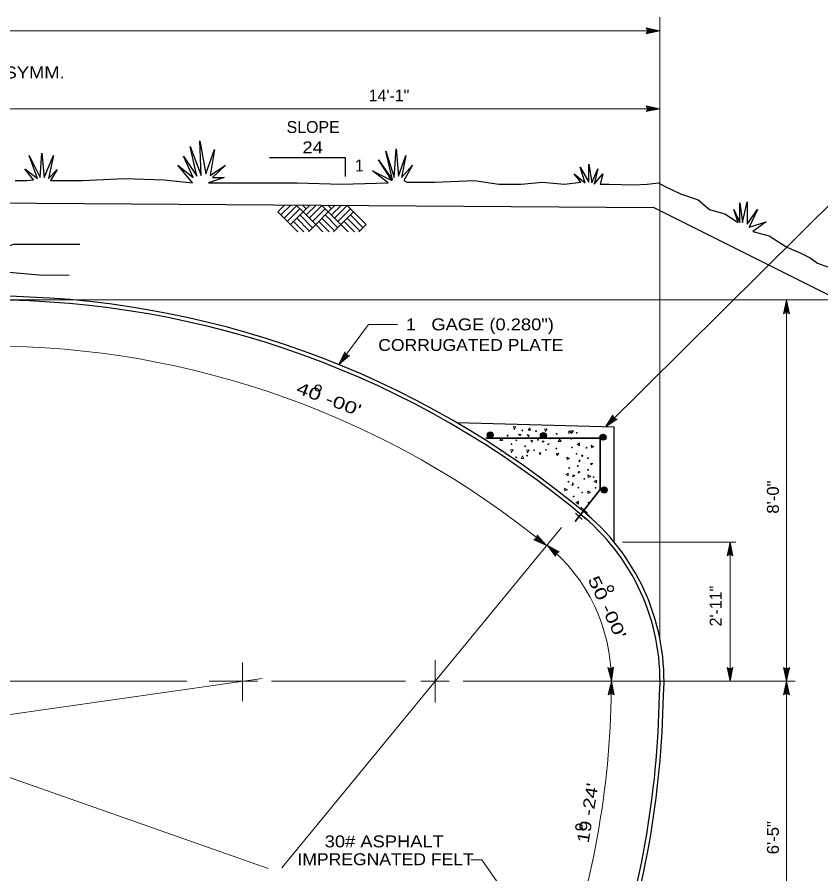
# Model space of a CAD drawing. Extents: x -24.3 to 17.7, y -17.6 to 12.4.
# Drawn here: x -9.61 to -1.17, y -10.08 to -1.09 of the extents above; entities that cross this region are included whole.
import ezdxf
from ezdxf.enums import TextEntityAlignment as Align

# ---------------------------------------------------------------- set-up
doc = ezdxf.new("R2010")
doc.units = 0
doc.header["$LTSCALE"] = 0.05
doc.layers.add('1', color=7, linetype='Continuous', lineweight=13)
doc.layers.add('2', color=7, linetype='Continuous', lineweight=13)

msp = doc.modelspace()

# ---------------------------------------------------------------- linework, layer by layer
at = {"layer": '1'}
for p, q in [((-2.86269, -7.6306), (-2.86269, -1.0886)), ((-16.95069, -1.2326), (-2.86269, -1.2326)), ((-2.86269, -1.2326), (-3.00669, -1.2016)), ((-2.86269, -1.2326), (-3.00669, -1.2636)), ((-2.89969, -1.2326), (-2.99369, -1.2126)), ((-2.98469, -1.2326), (-2.99369, -1.2126)), ((-2.89969, -1.2326), (-2.99369, -1.2526)), ((-2.99369, -1.2526), (-2.98469, -1.2326)), ((-2.93569, -1.2326), (-2.98069, -1.2236)), ((-2.97669, -1.2326), (-2.98069, -1.2236)), ((-2.93569, -1.2326), (-2.98069, -1.2426)), ((-2.98069, -1.2426), (-2.97669, -1.2326)), ((-2.86269, -2.0496), (-3.00669, -2.0186)), ((-2.86269, -2.0496), (-3.00669, -2.0806)), ((-2.89969, -2.0496), (-2.99369, -2.0296)), ((-2.98469, -2.0496), (-2.99369, -2.0296)), ((-2.89969, -2.0496), (-2.99369, -2.0696)), ((-2.99369, -2.0696), (-2.98469, -2.0496)), ((-2.93569, -2.0496), (-2.98069, -2.0406)), ((-2.97669, -2.0496), (-2.98069, -2.0406)), ((-2.93569, -2.0496), (-2.98069, -2.0596)), ((-2.98069, -2.0596), (-2.97669, -2.0496)), ((-3.43569, -5.3886), (-0.97569, -2.9496)), ((-6.87269, -3.1326), (-6.80169, -3.0616)), ((-6.83969, -3.1656), (-6.73569, -3.0616)), ((-6.80669, -3.1986), (-6.67369, -3.0666)), ((-6.77369, -3.2326), (-6.64069, -3.0996)), ((-6.74069, -3.2656), (-6.60769, -3.1326)), ((-6.60769, -3.1326), (-6.67869, -3.0616)), ((-6.57469, -3.0996), (-6.61269, -3.0616)), ((-6.60769, -3.1326), (-6.53669, -3.0616)), ((-6.60769, -3.1326), (-6.53669, -3.0616)), ((-6.47469, -3.2656), (-6.60769, -3.1326)), ((-6.57469, -3.1656), (-6.47069, -3.0616)), ((-6.54169, -3.0666), (-6.54669, -3.0616)), ((-6.54169, -3.1986), (-6.40869, -3.0666)), ((-6.50869, -3.2326), (-6.37569, -3.0996)), ((-6.47469, -3.2656), (-6.34269, -3.1326)), ((-6.34269, -3.1326), (-6.41369, -3.0616)), ((-6.30969, -3.0996), (-6.34769, -3.0616)), ((-6.34269, -3.1326), (-6.27169, -3.0616)), ((-6.30969, -3.1656), (-6.20469, -3.0616)), ((-6.27669, -3.0666), (-6.28069, -3.0616)), ((-6.27669, -3.1986), (-6.14369, -3.0666)), ((-6.24269, -3.2326), (-6.11069, -3.0996)), ((-6.20969, -3.2656), (-6.07769, -3.1326)), ((-6.07769, -3.1326), (-6.14869, -3.0616)), ((-5.94469, -3.2656), (-6.07769, -3.1326)), ((-6.59769, -3.3416), (-6.70769, -3.2326)), ((-6.54169, -3.3316), (-6.67369, -3.1986)), ((-6.50869, -3.2986), (-6.64069, -3.1656)), ((-6.33269, -3.3416), (-6.44169, -3.2326)), ((-6.27669, -3.3316), (-6.40869, -3.1986)), ((-6.24269, -3.2986), (-6.37569, -3.1656)), ((-6.06669, -3.3416), (-6.17669, -3.2326)), ((-6.01069, -3.3316), (-6.14369, -3.1986)), ((-5.97769, -3.2986), (-6.11069, -3.1656)), ((-6.55169, -3.3416), (-6.47469, -3.2656)), ((-6.39869, -3.3416), (-6.47469, -3.2656)), ((-6.28669, -3.3416), (-6.20969, -3.2656)), ((-6.02169, -3.3416), (-5.94469, -3.2656)), ((-9.90969, -4.0576), (-0.82769, -4.0576)), ((-1.53569, -4.0576), (-1.56669, -4.2016)), ((-1.53569, -4.0946), (-1.55569, -4.1886)), ((-1.53569, -4.1306), (-1.54469, -4.1756)), ((-1.53569, -4.0576), (-1.50469, -4.2016)), ((-1.53569, -4.0946), (-1.51569, -4.1886)), ((-1.53569, -4.1306), (-1.52569, -4.1756)), ((-1.53569, -4.1796), (-1.55569, -4.1886)), ((-1.53569, -4.1716), (-1.54469, -4.1756)), ((-1.52569, -4.1756), (-1.53569, -4.1716)), ((-1.51569, -4.1886), (-1.53569, -4.1796)), ((-5.92169, -4.3166), (-5.61569, -4.3166)), ((-6.23169, -4.7366), (-6.12169, -4.6396)), ((-6.20969, -4.7066), (-6.16969, -4.6196)), ((-6.20969, -4.7066), (-6.13769, -4.6426)), ((-6.18869, -4.6776), (-6.16969, -4.6356)), ((-6.18869, -4.6776), (-6.15469, -4.6466)), ((-6.16969, -4.6196), (-6.15969, -4.6386)), ((-6.16969, -4.6356), (-6.16369, -4.6446)), ((-6.16369, -4.6446), (-6.15469, -4.6466)), ((-6.15969, -4.6386), (-6.13769, -4.6426)), ((-3.43569, -5.3886), (-3.35569, -5.2656)), ((-3.40969, -5.3626), (-3.35669, -5.2826)), ((-3.38369, -5.3376), (-3.35869, -5.2986)), ((-3.35869, -5.2986), (-3.35469, -5.3086)), ((-3.35669, -5.2826), (-3.34869, -5.3026)), ((-3.34869, -5.3026), (-3.32869, -5.3106)), ((-3.43569, -5.3886), (-3.31169, -5.3096)), ((-3.40969, -5.3626), (-3.32869, -5.3106)), ((-3.38369, -5.3376), (-3.34569, -5.3116)), ((-3.35469, -5.3086), (-3.34569, -5.3116)), ((-6.82969, -10.0186), (-3.89669, -6.4466)), ((-4.16969, -6.5746), (-4.15069, -6.5646)), ((-4.15069, -6.5646), (-4.14669, -6.5426)), ((-4.05269, -6.6366), (-4.14969, -6.5266)), ((-4.08269, -6.6146), (-4.14669, -6.5426)), ((-4.14469, -6.5686), (-4.14269, -6.5596)), ((-4.11169, -6.5936), (-4.14269, -6.5596)), ((-4.05269, -6.6366), (-4.18669, -6.5756)), ((-4.08269, -6.6146), (-4.16969, -6.5746)), ((-4.15369, -6.5746), (-4.14469, -6.5686)), ((-4.11169, -6.5936), (-4.15369, -6.5746)), ((-4.04769, -6.6306), (-3.91769, -6.7006)), ((-4.04769, -6.6306), (-3.95869, -6.7476)), ((-4.01969, -6.6546), (-3.93569, -6.7006)), ((-4.01969, -6.6546), (-3.96169, -6.7306)), ((-3.25669, -6.5996), (-2.06769, -6.5996)), ((-2.12769, -6.5996), (-2.15869, -6.7436)), ((-2.12769, -6.6366), (-2.14769, -6.7306)), ((-2.12769, -8.0586), (-2.12769, -6.5996)), ((-2.12769, -6.5996), (-2.09669, -6.7436)), ((-2.12769, -6.6366), (-2.10769, -6.7306)), ((-3.99269, -6.6786), (-3.96369, -6.7146)), ((-3.99269, -6.6786), (-3.95169, -6.6996)), ((-3.96069, -6.7046), (-3.96369, -6.7146)), ((-3.95469, -6.7096), (-3.96169, -6.7306)), ((-3.95169, -6.6996), (-3.96069, -6.7046)), ((-3.93569, -6.7006), (-3.95469, -6.7096)), ((-2.12769, -6.7216), (-2.14769, -6.7306)), ((-2.12769, -6.6726), (-2.13669, -6.7176)), ((-2.12769, -6.7136), (-2.13669, -6.7176)), ((-2.12769, -6.6726), (-2.11769, -6.7176)), ((-2.11769, -6.7176), (-2.12769, -6.7136)), ((-2.10769, -6.7306), (-2.12769, -6.7216)), ((-7.24269, -8.2706), (-7.24269, -7.8636)), ((-5.22169, -8.2826), (-5.22169, -7.8386)), ((-3.37269, -8.0586), (-3.34869, -7.9136)), ((-3.37269, -8.0586), (-3.41069, -7.9166)), ((-3.37469, -8.0216), (-3.39969, -7.9286)), ((-3.39969, -7.9286), (-3.37869, -7.9366)), ((-3.37669, -7.9856), (-3.38869, -7.9416)), ((-3.38869, -7.9416), (-3.37869, -7.9446)), ((-3.37869, -7.9366), (-3.35969, -7.9266)), ((-3.37869, -7.9446), (-3.36969, -7.9406)), ((-3.37669, -7.9856), (-3.36969, -7.9406)), ((-3.37469, -8.0216), (-3.35969, -7.9266)), ((-2.12769, -8.0586), (-2.15869, -7.9146)), ((-2.12769, -8.0216), (-2.14769, -7.9276)), ((-2.14769, -7.9276), (-2.12769, -7.9366)), ((-2.12769, -7.9856), (-2.13769, -7.9406)), ((-2.13769, -7.9406), (-2.12769, -7.9446)), ((-2.12769, -8.0586), (-2.09669, -7.9146)), ((-2.12769, -8.0216), (-2.10769, -7.9276)), ((-2.12769, -7.9366), (-2.10769, -7.9276)), ((-2.12769, -7.9856), (-2.11869, -7.9406)), ((-2.12769, -7.9446), (-2.11869, -7.9406)), ((-1.53569, -8.0586), (-1.56669, -7.9146)), ((-1.53569, -8.0216), (-1.55569, -7.9276)), ((-1.55569, -7.9276), (-1.53569, -7.9366)), ((-1.53569, -7.9856), (-1.54569, -7.9406)), ((-1.54569, -7.9406), (-1.53569, -7.9446)), ((-1.53569, -8.0586), (-1.50469, -7.9146)), ((-1.53569, -8.0216), (-1.51569, -7.9276)), ((-1.53569, -7.9366), (-1.51569, -7.9276)), ((-1.53569, -7.9856), (-1.52669, -7.9406)), ((-1.53569, -7.9446), (-1.52669, -7.9406)), ((-6.97269, -10.0246), (-12.66869, -8.0256)), ((-12.31469, -8.0586), (-7.82569, -8.0586)), ((-7.59069, -8.0586), (-7.08569, -8.0586)), ((-6.93769, -8.0586), (-5.53169, -8.0586)), ((-5.37069, -8.0586), (-5.07469, -8.0586)), ((-4.92669, -8.0586), (-1.44469, -8.0586)), ((-3.37269, -8.0586), (-3.40569, -8.2026)), ((-3.37269, -8.0586), (-3.34369, -8.2026)), ((-1.53569, -8.0586), (-1.56669, -8.2026)), ((-1.53569, -8.0586), (-1.50469, -8.2026)), ((-3.37369, -8.0956), (-3.39469, -8.1896)), ((-3.37469, -8.1806), (-3.39469, -8.1896)), ((-3.37369, -8.1316), (-3.38369, -8.1766)), ((-3.37469, -8.1726), (-3.38369, -8.1766)), ((-3.36469, -8.1766), (-3.37469, -8.1726)), ((-3.35469, -8.1896), (-3.37469, -8.1806)), ((-3.37369, -8.0956), (-3.35469, -8.1896)), ((-3.37369, -8.1316), (-3.36469, -8.1766)), ((-1.53569, -8.0956), (-1.55569, -8.1896)), ((-1.53569, -8.1806), (-1.55569, -8.1896)), ((-1.53569, -8.1316), (-1.54469, -8.1766)), ((-1.53569, -8.1726), (-1.54469, -8.1766)), ((-1.53569, -8.0956), (-1.51569, -8.1896)), ((-1.53569, -8.1316), (-1.52569, -8.1766)), ((-1.52569, -8.1766), (-1.53569, -8.1726)), ((-1.51569, -8.1896), (-1.53569, -8.1806))]:
    msp.add_line(p, q, dxfattribs=at)
at = {"layer": '1', "lineweight": 35}
for p, q in [((-3.62169, -6.2966), (-3.69469, -6.2326)), ((-3.67769, -6.3606), (-3.75069, -6.2966))]:
    msp.add_line(p, q, dxfattribs=at)
at = {"layer": '1'}
for points in [[(-3.00669, -1.2636), (-2.99269, -1.2326), (-3.00669, -1.2016)], [(-16.95069, -2.0496), (-9.90769, -2.0496), (-2.86269, -2.0496)], [(-3.00669, -2.0806), (-2.99269, -2.0496), (-3.00669, -2.0186)], [(-6.66369, -3.3416), (-6.74069, -3.2656), (-6.87269, -3.1326)], [(-6.13369, -3.3416), (-6.34269, -3.1326), (-6.27169, -3.0616)], [(-1.53569, -12.5166), (-1.53569, -11.9936), (-1.53569, -11.2666), (-1.53569, -8.0586), (-1.53569, -4.0576)], [(-1.50469, -4.2016), (-1.53569, -4.1876), (-1.56669, -4.2016)], [(-5.92169, -4.3166), (-6.23169, -4.7366), (-6.17069, -4.6026)], [(-6.17069, -4.6026), (-6.15469, -4.6316), (-6.12169, -4.6396)], [(-3.35569, -5.2656), (-3.34369, -5.2966), (-3.31169, -5.3096)], [(-4.18669, -6.5756), (-4.15769, -6.5596), (-4.14969, -6.5266)], [(-3.91769, -6.7006), (-3.94869, -6.7156), (-3.95869, -6.7476)], [(-2.09669, -6.7436), (-2.12769, -6.7296), (-2.15869, -6.7436)], [(-3.41069, -7.9166), (-3.37969, -7.9286), (-3.34869, -7.9136)], [(-2.15869, -7.9146), (-2.12769, -7.9286), (-2.09669, -7.9146)], [(-1.56669, -7.9146), (-1.53569, -7.9286), (-1.50469, -7.9146)], [(-7.03769, -8.0296), (-16.85269, -9.4346), (-16.71469, -9.3836)], [(-3.34369, -8.2026), (-3.37469, -8.1886), (-3.40569, -8.2026)], [(-1.50469, -8.2026), (-1.53569, -8.1886), (-1.56669, -8.2026)], [(-4.84869, -9.9336), (-4.73269, -9.9336), (-3.74269, -11.3566), (-3.85069, -11.2556)]]:
    msp.add_lwpolyline(points, dxfattribs=at)
at = {"layer": '1', "lineweight": 25}
for points in [[(-9.62769, -2.8046), (-9.50369, -2.8046), (-9.43369, -2.7966), (-9.52669, -2.6806), (-9.39469, -2.7816), (-9.47969, -2.5406), (-9.36369, -2.7736), (-9.34869, -2.5176), (-9.32469, -2.7736), (-9.22469, -2.5406), (-9.27869, -2.7816), (-9.18569, -2.6886), (-9.25569, -2.8046), (-8.92269, -2.8046), (-8.48069, -2.7816), (-8.06269, -2.7966), (-7.76769, -2.8276), (-7.92269, -2.6416), (-7.76069, -2.7736), (-7.86069, -2.5486), (-7.72169, -2.7576), (-7.79069, -2.4476), (-7.67469, -2.7506), (-7.69069, -2.3856), (-7.62869, -2.7346), (-7.53569, -2.4786), (-7.58169, -2.7506), (-7.41969, -2.6416), (-7.55869, -2.7736), (-7.43469, -2.7736), (-7.59769, -2.8276), (-7.02469, -2.8276), (-6.66769, -2.8276), (-6.20269, -2.8426), (-5.71469, -2.8276), (-5.87769, -2.7036), (-5.67569, -2.8046), (-5.81569, -2.5876), (-5.66869, -2.7966), (-5.73769, -2.4946), (-5.65269, -2.7736), (-5.62969, -2.4716), (-5.60669, -2.7576), (-5.52869, -2.5406), (-5.57569, -2.7736), (-5.45969, -2.6416), (-5.55169, -2.8046), (-5.51369, -2.8196), (-5.22669, -2.8196), (-4.80869, -2.8046), (-4.55269, -2.8426), (-4.32069, -2.8426), (-4.09569, -2.8196), (-3.86369, -2.8426), (-3.69269, -2.8196), (-3.76269, -2.7346), (-3.64669, -2.8276), (-3.70069, -2.6646), (-3.60769, -2.8196), (-3.60769, -2.6336), (-3.57669, -2.8276), (-3.51469, -2.6806), (-3.55369, -2.8426), (-3.46069, -2.7346), (-3.49169, -2.8426), (-3.39869, -2.8426), (-3.13469, -2.8506), (-2.99569, -2.8426), (-2.87969, -2.8276), (-2.80969, -2.8666), (-2.64669, -2.9436), (-2.46069, -3.0056), (-2.34469, -3.1066), (-2.18169, -3.1526), (-2.04269, -3.2456), (-2.08869, -3.1066), (-2.02669, -3.2456), (-2.02669, -3.0366), (-1.99569, -3.2456), (-1.94969, -3.0286), (-1.94969, -3.2616), (-1.84069, -3.1066), (-1.92669, -3.2926), (-1.74769, -3.2386), (-1.88769, -3.3386), (-1.71669, -3.3856), (-1.53169, -3.5016), (-1.39169, -3.5636)], [(-6.16269, -2.7616), (-6.16269, -2.5666), (-6.96069, -2.5666)], [(-9.91169, -3.0386), (-2.92769, -3.0886), (0.66231, -4.8826)], [(-10.16769, -3.5166), (-10.05169, -3.5216), (-9.79869, -3.5216), (-9.64269, -3.4726), (-9.24269, -3.4726), (-8.95069, -3.4726)], [(-1.39169, -3.5636), (-1.28669, -3.6146), (-1.20969, -3.6696), (-1.09569, -3.7136)], [(-9.73469, -3.7606), (-9.37669, -3.7926), (-9.06069, -3.7976)], [(-3.34269, -6.5996), (-3.34269, -5.3916), (-4.99369, -5.3466)]]:
    msp.add_lwpolyline(points, dxfattribs=at)
at = {"layer": '1', "lineweight": 35}
msp.add_lwpolyline([(-4.68969, -5.5066), (-3.48869, -5.5066), (-3.48869, -6.0486), (-3.75369, -6.3826)], dxfattribs=at)
at = {"layer": '1', "lineweight": 25}
for centre, radius in [((-6.44869, -4.9816), 0.03178), ((-4.64418, -5.4754), 0.0319), ((-4.64418, -5.4754), 0.02658), ((-4.64418, -5.4754), 0.02215), ((-4.64418, -5.4754), 0.01846), ((-4.64418, -5.4754), 0.01538), ((-4.64418, -5.4754), 0.01282), ((-4.64418, -5.4754), 0.01068), ((-4.64418, -5.4754), 0.0089), ((-4.08556, -5.48103), 0.0319), ((-4.08556, -5.48103), 0.02658), ((-4.08556, -5.48103), 0.02215), ((-4.08556, -5.48103), 0.01846), ((-4.08556, -5.48103), 0.01538), ((-4.08556, -5.48103), 0.01282), ((-4.08556, -5.48103), 0.01068), ((-4.08556, -5.48103), 0.0089), ((-3.45924, -5.49794), 0.0319), ((-3.45924, -5.49794), 0.02658), ((-3.45924, -5.49794), 0.02215), ((-3.45924, -5.49794), 0.01846), ((-3.45924, -5.49794), 0.01538), ((-3.45924, -5.49794), 0.01282), ((-3.45924, -5.49794), 0.01068), ((-3.45924, -5.49794), 0.0089), ((-3.44795, -6.05093), 0.0319), ((-3.44795, -6.05093), 0.02658), ((-3.44795, -6.05093), 0.02215), ((-3.44795, -6.05093), 0.01846), ((-3.44795, -6.05093), 0.01538), ((-3.44795, -6.05093), 0.01282), ((-3.44795, -6.05093), 0.01068), ((-3.44795, -6.05093), 0.0089), ((-3.38169, -7.0876), 0.03178), ((-3.71269, -9.5886), 0.03178)]:
    msp.add_circle(centre, radius, dxfattribs=at)
for centre, radius, start, end in [((-9.90906, -13.7666), 9.74984, 49.71979, 130.09764), ((-9.90906, -13.7666), 9.70818, 49.71979, 130.09764), ((-5.11747, -8.05836), 2.25547, 356.27175, 49.61534), ((-5.11747, -8.05836), 2.29713, 356.27175, 49.61534), ((-12.57569, -8.05836), 9.70818, 340.66927, 359.12919), ((-12.57569, -8.05836), 9.74984, 340.66927, 359.12919)]:
    msp.add_arc(centre, radius, start, end, dxfattribs=at)
at = {"layer": '1'}
for centre, radius, start, end in [((-9.90869, -13.7666), 9.22657, 50.60311, 90), ((-5.22169, -8.0586), 1.849, 0, 50.57701), ((-12.59669, -8.0506), 9.224, 340.65884, 359.95031)]:
    msp.add_arc(centre, radius, start, end, dxfattribs=at)
at = {"layer": '2'}
for p, q in [((-4.13169, -5.6656), (-4.11569, -5.6786)), ((-3.58469, -5.7896), (-3.57069, -5.7746))]:
    msp.add_line(p, q, dxfattribs=at)
for points in [[(-4.38969, -5.4166), (-4.40369, -5.3896), (-4.37569, -5.3866), (-4.39669, -5.4166)], [(-4.34469, -5.4706), (-4.33169, -5.4786), (-4.31969, -5.4706), (-4.35169, -5.4656)], [(-4.23269, -5.4026), (-4.24569, -5.4256), (-4.21669, -5.4256), (-4.23269, -5.3986)], [(-4.06169, -5.4386), (-4.07569, -5.4126), (-4.04769, -5.4096), (-4.06869, -5.4386)], [(-3.79069, -5.4446), (-3.81769, -5.4576), (-3.82069, -5.4306), (-3.79069, -5.4506)], [(-3.78569, -5.4586), (-3.79969, -5.4326), (-3.77169, -5.4296), (-3.79269, -5.4586)], [(-4.52869, -5.5106), (-4.54169, -5.5326), (-4.51269, -5.5326), (-4.52869, -5.5056)], [(-4.09769, -5.5396), (-4.08869, -5.5506), (-4.07769, -5.5396), (-4.09569, -5.5376)], [(-4.04369, -5.5736), (-4.03069, -5.5786), (-4.02369, -5.5646), (-4.04369, -5.5706)], [(-3.91669, -5.5216), (-3.92969, -5.5446), (-3.90069, -5.5446), (-3.91669, -5.5166)], [(-3.72869, -5.5746), (-3.70569, -5.5886), (-3.70569, -5.5586), (-3.73269, -5.5746)], [(-4.41669, -5.6586), (-4.42969, -5.6316), (-4.40269, -5.6286), (-4.42369, -5.6586)], [(-4.25069, -5.6606), (-4.26369, -5.6346), (-4.23669, -5.6316), (-4.25769, -5.6606)], [(-4.11569, -5.6806), (-4.11169, -5.6606), (-4.13169, -5.6606)], [(-3.93869, -5.6946), (-3.95169, -5.6676), (-3.92469, -5.6646), (-3.94569, -5.6946)], [(-3.55569, -5.5966), (-3.58269, -5.6106), (-3.58469, -5.5826), (-3.55569, -5.6036)], [(-4.30669, -5.6986), (-4.31969, -5.7216), (-4.29069, -5.7216), (-4.30669, -5.6946)], [(-3.81069, -5.7206), (-3.83769, -5.7336), (-3.84069, -5.7066), (-3.81069, -5.7266)], [(-3.71069, -5.7566), (-3.69869, -5.7466), (-3.71069, -5.7356), (-3.71269, -5.7536)], [(-3.67669, -5.7026), (-3.67169, -5.6886), (-3.68569, -5.6826), (-3.67869, -5.7026)], [(-3.56869, -5.7746), (-3.58869, -5.7696), (-3.58869, -5.7896)], [(-3.84669, -5.8906), (-3.82469, -5.9046), (-3.82469, -5.8746), (-3.85169, -5.8906)], [(-3.58869, -5.9086), (-3.61569, -5.9226), (-3.61869, -5.8946), (-3.58869, -5.9156)], [(-3.77969, -6.0026), (-3.77069, -5.9896), (-3.77969, -5.9786), (-3.78469, -6.0096)], [(-3.55069, -5.9646), (-3.52869, -5.9786), (-3.52869, -5.9486), (-3.55569, -5.9646)], [(-3.83369, -6.0486), (-3.86069, -6.0616), (-3.86269, -6.0346), (-3.83369, -6.0546)], [(-3.59169, -6.0746), (-3.61869, -6.0886), (-3.62069, -6.0606), (-3.59169, -6.0816)], [(-3.73969, -6.1866), (-3.71669, -6.2006), (-3.71669, -6.1706), (-3.74469, -6.1866)]]:
    msp.add_lwpolyline(points, dxfattribs=at)
for points in [[(-4.25769, -5.4706), (-4.24369, -5.4926), (-4.23669, -5.4766)], [(-4.21769, -5.5276), (-4.20369, -5.5506), (-4.19669, -5.5346)], [(-3.77969, -5.9156), (-3.75669, -5.9026), (-3.77269, -5.8946)], [(-3.72269, -5.8756), (-3.69969, -5.8626), (-3.71569, -5.8546)]]:
    msp.add_lwpolyline(points, close=True, dxfattribs=at)
for centre in [(-4.46136, -5.48132), (-4.30669, -5.42732), (-4.1627, -5.43399), (-3.94737, -5.46332), (-3.7347, -5.45307), (-4.42069, -5.57132), (-4.36936, -5.53065), (-4.1427, -5.52598), (-4.0147, -5.51065), (-3.7947, -5.51532), (-4.52669, -5.63865), (-4.27736, -5.59332), (-4.18336, -5.63398), (-4.06003, -5.63132), (-3.95003, -5.61598), (-3.7867, -5.60573), (-3.63404, -5.6084), (-4.37136, -5.70998), (-4.25736, -5.69198), (-3.73937, -5.67307), (-3.6187, -5.7184), (-3.81603, -5.82106), (-3.72404, -5.80106), (-3.61604, -5.84173), (-3.6567, -5.93573), (-3.55804, -5.91573), (-3.8227, -5.96506), (-3.71937, -6.02773), (-3.54004, -6.02973), (-3.6787, -6.07906), (-3.7687, -6.11973), (-3.61137, -6.18506)]:
    msp.add_circle(centre, 0.00433, dxfattribs=at)

# ---------------------------------------------------------------- texts
at = {"layer": '1', "width": 1.15}
for s, p in [('C SYMM.', (-9.93069, -1.7316)), ('24', (-6.61369, -2.5186)), ('1   GAGE (0.280")', (-5.52869, -4.3766))]:
    msp.add_text(s, height=0.125, dxfattribs=at).set_placement(p)
at = {"layer": '1'}
for s, p in [('14\'-1"', (-5.70569, -1.9736)), ('SLOPE', (-6.50119, -2.3046))]:
    msp.add_text(s, height=0.125, dxfattribs=at).set_placement(p, align=Align.CENTER)
msp.add_text('1', height=0.125, dxfattribs=at).set_placement((-6.06269, -2.7086))
for s, width, p in [('CORRUGATED PLATE', 1.1, (-4.84769, -4.5926)), ('30# ASPHALT', 1.15, (-5.75519, -9.8036)), ('IMPREGNATED FELT', 1.1, (-5.74119, -9.9906))]:
    msp.add_text(s, height=0.125, dxfattribs=dict(at, width=width)).set_placement(p, align=Align.CENTER)
for s, rotation, width, p in [("40 -00'", 339.475, 1.4, (-6.35753, -5.15555)), ('8\'-0"', 90, 1.05, (-1.61569, -6.1266)), ("50 -00'", 295.174, 1.4, (-3.47237, -7.31088)), ("19 -24'", 80.349, 1.25, (-3.55972, -9.45321)), ('6\'-5"', 90, 1.05, (-1.61569, -9.7021))]:
    msp.add_text(s, height=0.125, rotation=rotation, dxfattribs=dict(at, width=width)).set_placement(p, align=Align.CENTER)
msp.add_text('2\'-11"', height=0.125, rotation=90, dxfattribs=at).set_placement((-2.21669, -7.2706), align=Align.CENTER)

doc.saveas('drawing.dxf')
